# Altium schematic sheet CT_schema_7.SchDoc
size 408 x 379 mm
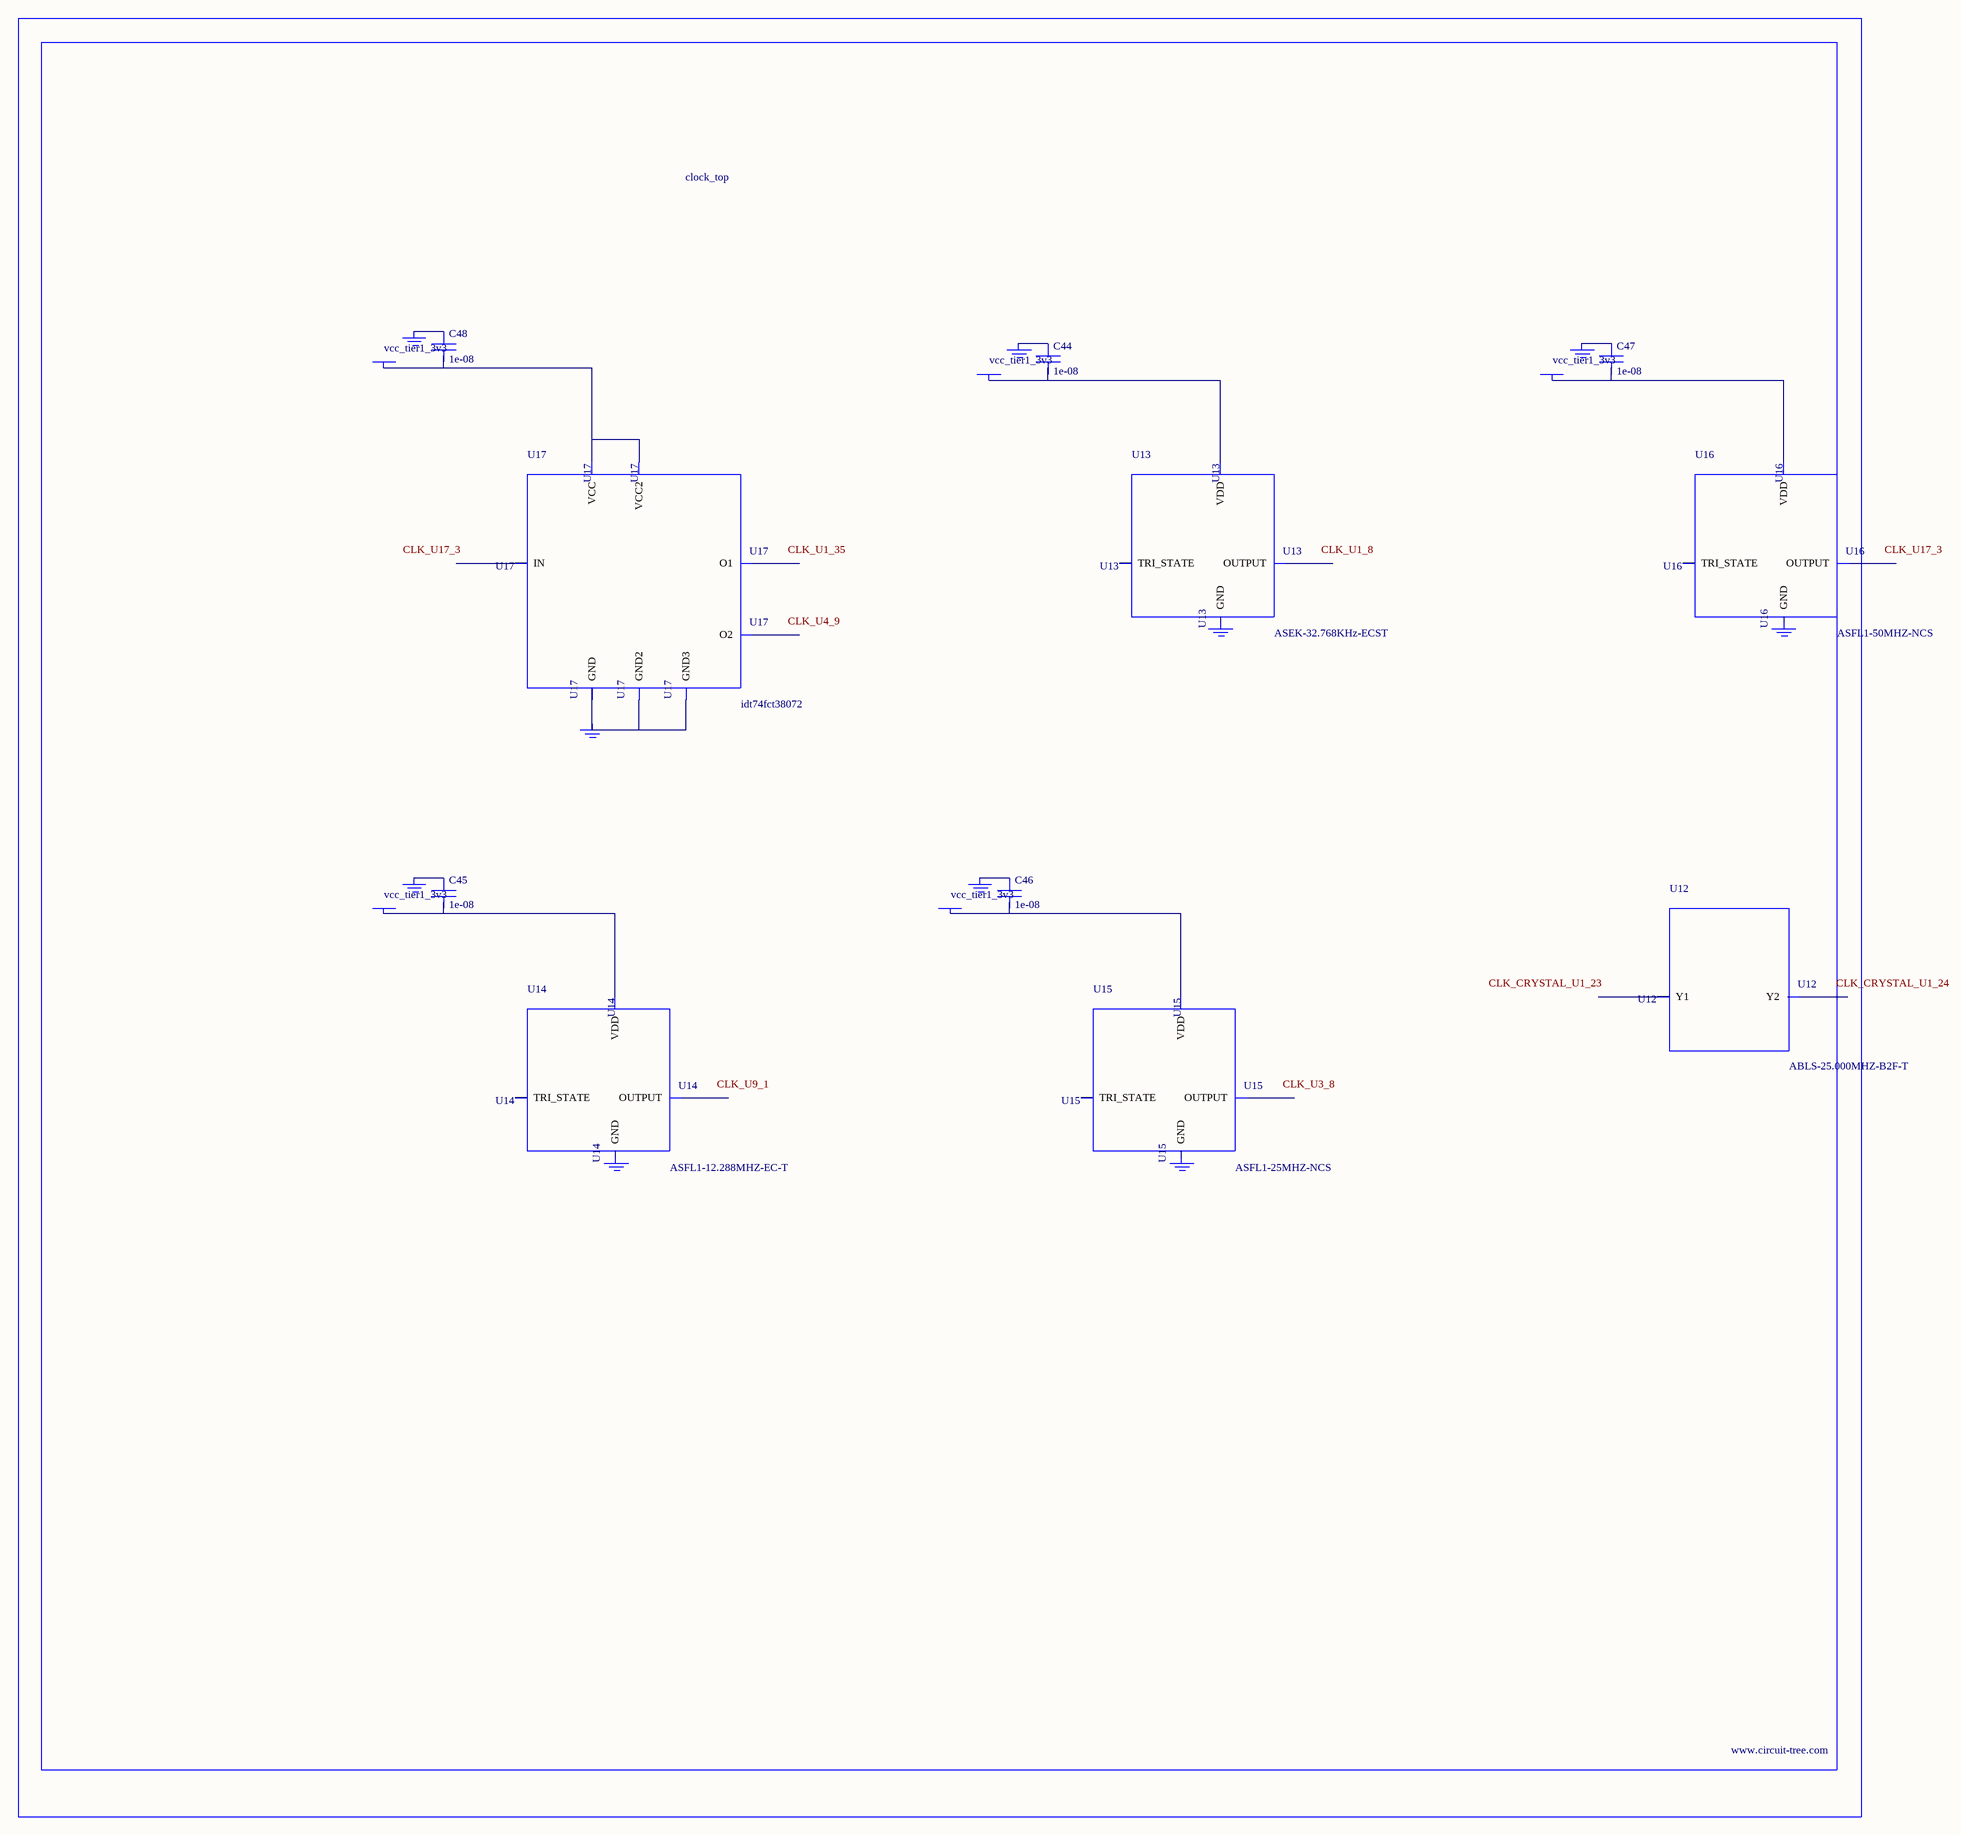
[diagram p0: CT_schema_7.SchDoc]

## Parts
BORDER6  (no value)
C44  1e-08  [C0402]
C45  1e-08  [C0402]
C46  1e-08  [C0402]
C47  1e-08  [C0402]
C48  1e-08  [C0402]
GND_INSTANCE_6_0  (no value)
GND_INSTANCE_6_1  (no value)
GND_INSTANCE_6_2  (no value)
GND_INSTANCE_6_3  (no value)
GND_INSTANCE_6_4  (no value)
GND_INSTANCE_6_5  (no value)
GND_INSTANCE_6_6  (no value)
GND_INSTANCE_6_7  (no value)
GND_INSTANCE_6_8  (no value)
GND_INSTANCE_6_9  (no value)
POWER_INSTANCE_6_0  vcc_tier1_3v3
POWER_INSTANCE_6_1  vcc_tier1_3v3
POWER_INSTANCE_6_2  vcc_tier1_3v3
POWER_INSTANCE_6_3  vcc_tier1_3v3
POWER_INSTANCE_6_4  vcc_tier1_3v3
U12  ABLS-25.000MHZ-B2F-T  [ABLS-25.000MHZ-B2F-T]
U13  ASEK-32.768KHz-ECST  [ASEK]
U14  ASFL1-12.288MHZ-EC-T  [ASFL1]
U15  ASFL1-25MHZ-NCS  [ASFL1]
U16  ASFL1-50MHZ-NCS  [ASFL1]
U17  idt74fct38072  [IDT74FCT38072]

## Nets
NetC44_1: C44.1 GND_INSTANCE_6_0.0(GND)
NetC44_2: C44.2 POWER_INSTANCE_6_0.0(PWR) U13.4(VDD)
NetC45_1: C45.1 GND_INSTANCE_6_2.0(GND)
NetC45_2: C45.2 POWER_INSTANCE_6_1.0(PWR) U14.4(VDD)
NetC46_1: C46.1 GND_INSTANCE_6_4.0(GND)
NetC46_2: C46.2 POWER_INSTANCE_6_2.0(PWR) U15.4(VDD)
NetC47_1: C47.1 GND_INSTANCE_6_6.0(GND)
NetC47_2: C47.2 POWER_INSTANCE_6_3.0(PWR) U16.4(VDD)
NetC48_1: C48.1 GND_INSTANCE_6_8.0(GND)
NetC48_2: C48.2 POWER_INSTANCE_6_4.0(PWR) U17.1(VCC) U17.2(VCC2)
NetGND_INSTANCE_6_9_0: GND_INSTANCE_6_9.0(GND) U17.4(GND) U17.5(GND2) U17.8(GND3)

Not connected (* = marked no-connect by the designer): GND_INSTANCE_6_1 0(GND); GND_INSTANCE_6_3 0(GND); GND_INSTANCE_6_5 0(GND); GND_INSTANCE_6_7 0(GND); U12 1(Y1) 2(Y2); U13 1(TRI_STATE) 2(GND) 3(OUTPUT); U14 1(TRI_STATE) 2(GND) 3(OUTPUT); U15 1(TRI_STATE) 2(GND) 3(OUTPUT); U16 1(TRI_STATE) 2(GND) 3(OUTPUT); U17 3(IN) 6(O2) 7(O1)

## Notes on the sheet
- Labels drawn without touching a wire or pin: CLK_CRYSTAL_U1_23, CLK_CRYSTAL_U1_24, CLK_U1_8, CLK_U1_35, CLK_U3_8, CLK_U4_9, CLK_U9_1, CLK_U17_3

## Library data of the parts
BORDER6 = BORDER_PAGE6
C44-C48 = C0402C103K3RAC
GND_INSTANCE_6_0-GND_INSTANCE_6_9 = GND
POWER_INSTANCE_6_0-POWER_INSTANCE_6_4 = PWR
